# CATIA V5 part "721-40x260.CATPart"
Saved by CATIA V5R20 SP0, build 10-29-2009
Part number: 721-40x260
Definition: NONE
Nomenclature: 721-40x260
Source: Unknown
Description: 721-40x260
Bounding box of the stored display mesh (mm): x -120 to 140, y -35 to 35, z -35 to 35
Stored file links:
  C:\Users\Utente\Desktop\IO LAVORO\3D X SITO CF\X SITO\721\721-40x260.CATPart

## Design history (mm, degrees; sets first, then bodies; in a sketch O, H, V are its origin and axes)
Body1 "721-40x260" (main body)
  Solid1: solid without history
